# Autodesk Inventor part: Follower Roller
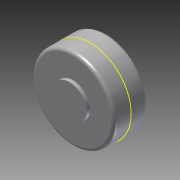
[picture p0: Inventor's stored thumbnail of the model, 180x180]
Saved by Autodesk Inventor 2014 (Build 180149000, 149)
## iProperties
Created: 2008-07
Part Number: Follower Roller
Document SubType Name: Modeling
Designer: tangg
Density: 7.85 g/cm^3
Material: Alloy Steel
Appearance: Steel
Author: tangg
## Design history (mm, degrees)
feature "Base1"
sketch "Sketch1"
  geometry: C1 r 3.81 at (0, 0) reference; 1 further point
  constraints: 1 other
  node "Project Cut Edges1"
body "Solid1"
